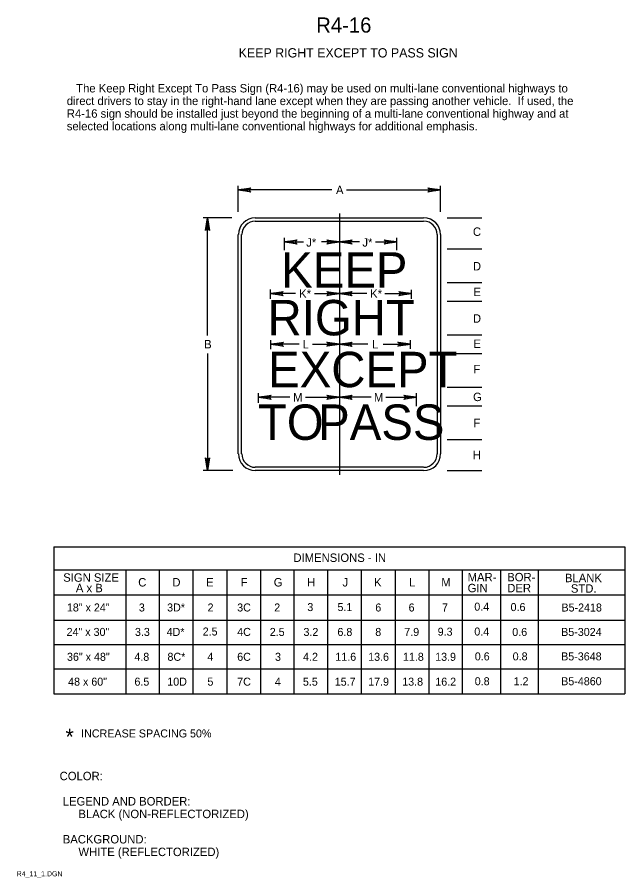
# Model space of a CAD drawing. Extents: x 0.013 to 0.193, y 0.004 to 0.259.
import ezdxf

# ---------------------------------------------------------------- set-up
doc = ezdxf.new("R2010")
doc.units = 0
for name, color, linetype in [('1', 7, 'Continuous'), ('11', 7, 'Continuous'), ('12', 7, 'Continuous'), ('2', 7, 'Continuous'), ('3', 7, 'Continuous')]:
    doc.layers.add(name, color=color, linetype=linetype)

# ---------------------------------------------------------------- blocks, each defined once
blk = doc.blocks.new('RARROW')
at = {"layer": '3'}
for p, q in [((-2.156, 0.285), (-2.2665, 0.384625)), ((-2.2665, 0.384625), (0, 0)), ((0, 0), (-2.2665, -0.379125)), ((-2.156, 0.285), (-2.075625, 0.12075)), ((0, 0), (-2.156, 0.285)), ((-2.14975, -0.2705), (0, 0)), ((-2.075625, 0.12075), (0, 0)), ((0, 0), (-2.074, -0.108)), ((-2.2665, -0.379125), (-2.14975, -0.2705)), ((-2.074, -0.108), (-2.14975, -0.2705))]:
    blk.add_line(p, q, dxfattribs=at)

msp = doc.modelspace()

# ---------------------------------------------------------------- linework, layer by layer
at = {"layer": '11'}
for p, q in [((0.08313, 0.19971), (0.13312, 0.19971)), ((0.07812, 0.12971), (0.07812, 0.19471)), ((0.13812, 0.19471), (0.13812, 0.12971)), ((0.13312, 0.12471), (0.08313, 0.12471))]:
    msp.add_line(p, q, dxfattribs=at)
for centre, start, end in [((0.08317, 0.1947), 90, 180), ((0.13317, 0.1947), 0, 90), ((0.08317, 0.1297), 180, 270), ((0.13317, 0.1297), 270, 0)]:
    msp.add_arc(centre, 0.005, start, end, dxfattribs=at)
at = {"layer": '3'}
for p, q in [((0.07812, 0.20147), (0.07812, 0.20921)), ((0.10587, 0.20796), (0.07812, 0.20796)), ((0.11025, 0.20796), (0.13812, 0.20796)), ((0.13812, 0.20147), (0.13812, 0.20921)), ((0.07625, 0.19971), (0.06775, 0.19971)), ((0.069, 0.16483), (0.069, 0.19971)), ((0.10812, 0.20096), (0.10812, 0.12346)), ((0.14012, 0.19971), (0.15038, 0.19971)), ((0.08313, 0.19871), (0.13312, 0.19871)), ((0.07913, 0.12971), (0.07913, 0.19471)), ((0.13712, 0.19471), (0.13712, 0.12971)), ((0.0918, 0.19005), (0.0918, 0.19377)), ((0.09186, 0.19252), (0.09753, 0.19252)), ((0.10877, 0.19252), (0.10285, 0.19252)), ((0.10812, 0.1939), (0.10812, 0.19127)), ((0.10812, 0.19252), (0.11188, 0.19314)), ((0.11168, 0.19296), (0.10812, 0.19252)), ((0.10812, 0.19252), (0.11156, 0.1927)), ((0.11313, 0.19252), (0.10812, 0.19252)), ((0.11156, 0.19232), (0.10812, 0.19252)), ((0.10812, 0.19252), (0.11169, 0.19206)), ((0.11188, 0.19189), (0.10812, 0.19252)), ((0.11413, 0.19252), (0.10812, 0.19252)), ((0.11156, 0.1927), (0.11168, 0.19296)), ((0.11169, 0.19206), (0.11156, 0.19232)), ((0.11188, 0.19314), (0.11168, 0.19296)), ((0.11169, 0.19206), (0.11188, 0.19189)), ((0.11887, 0.19252), (0.12514, 0.19252)), ((0.12157, 0.19299), (0.12139, 0.19315)), ((0.12139, 0.19315), (0.12514, 0.19252)), ((0.12514, 0.19252), (0.12139, 0.1919)), ((0.12139, 0.1919), (0.12158, 0.19208)), ((0.12157, 0.19299), (0.1217, 0.19272)), ((0.12514, 0.19252), (0.12157, 0.19299)), ((0.12158, 0.19208), (0.12514, 0.19252)), ((0.12171, 0.19234), (0.12158, 0.19208)), ((0.1217, 0.19272), (0.12514, 0.19252)), ((0.12514, 0.19252), (0.12171, 0.19234)), ((0.12514, 0.19005), (0.12514, 0.19377)), ((0.14012, 0.19046), (0.15038, 0.19046)), ((0.10812, 0.17921), (0.10812, 0.17596)), ((0.14012, 0.18046), (0.15038, 0.18046)), ((0.08773, 0.17571), (0.08773, 0.17846)), ((0.09508, 0.17721), (0.08816, 0.17721)), ((0.10072, 0.17721), (0.10812, 0.17721)), ((0.11623, 0.17721), (0.10867, 0.17721)), ((0.12165, 0.17721), (0.12903, 0.17721)), ((0.12948, 0.17569), (0.12948, 0.17831)), ((0.14012, 0.17496), (0.15038, 0.17496)), ((0.08775, 0.1607), (0.08775, 0.16345)), ((0.10812, 0.16358), (0.10812, 0.16096)), ((0.12926, 0.16082), (0.12926, 0.16345)), ((0.14012, 0.16496), (0.15038, 0.16496)), ((0.0962, 0.1622), (0.08818, 0.1622)), ((0.10012, 0.1622), (0.10812, 0.1622)), ((0.11658, 0.1622), (0.10812, 0.1622)), ((0.1211, 0.1622), (0.12926, 0.1622)), ((0.069, 0.15946), (0.069, 0.12471)), ((0.14012, 0.15946), (0.15038, 0.15946)), ((0.10812, 0.14846), (0.10812, 0.14521)), ((0.14012, 0.14946), (0.15038, 0.14946)), ((0.08415, 0.14483), (0.08415, 0.14771)), ((0.09346, 0.14646), (0.08415, 0.14646)), ((0.09804, 0.14646), (0.10812, 0.14646)), ((0.11757, 0.14646), (0.10812, 0.14646)), ((0.12188, 0.14646), (0.13104, 0.14646)), ((0.13104, 0.14383), (0.13104, 0.14771)), ((0.14012, 0.14396), (0.15038, 0.14396)), ((0.14012, 0.13396), (0.15038, 0.13396)), ((0.13312, 0.12571), (0.08313, 0.12571)), ((0.0765, 0.12471), (0.06775, 0.12471)), ((0.14012, 0.12471), (0.15038, 0.12471)), ((0.02344, 0.10213), (0.02344, 0.0585)), ((0.02344, 0.10212), (0.19281, 0.10212)), ((0.19281, 0.10212), (0.19281, 0.0585)), ((0.02344, 0.09525), (0.14459, 0.09525)), ((0.04474, 0.09525), (0.04474, 0.0585)), ((0.05469, 0.09525), (0.05469, 0.0585)), ((0.06469, 0.09525), (0.06469, 0.0585)), ((0.07469, 0.09525), (0.07469, 0.0585)), ((0.08469, 0.09525), (0.08469, 0.0585)), ((0.09465, 0.09525), (0.09465, 0.0585)), ((0.10459, 0.09525), (0.10459, 0.0585)), ((0.11459, 0.09525), (0.11459, 0.0585)), ((0.12464, 0.09525), (0.12464, 0.0585)), ((0.13464, 0.09525), (0.13464, 0.0585)), ((0.14459, 0.09525), (0.19281, 0.09525)), ((0.14459, 0.09525), (0.14459, 0.0585)), ((0.15597, 0.09525), (0.15597, 0.0585)), ((0.1671, 0.09525), (0.1671, 0.0585)), ((0.18005, 0.09525), (0.19281, 0.09525)), ((0.02344, 0.08787), (0.14459, 0.08787)), ((0.14459, 0.08787), (0.19281, 0.08787)), ((0.18005, 0.08788), (0.19281, 0.08788)), ((0.02344, 0.08037), (0.14459, 0.08037)), ((0.14459, 0.08037), (0.19281, 0.08037)), ((0.18005, 0.08038), (0.19281, 0.08038)), ((0.02344, 0.07312), (0.14459, 0.07312)), ((0.14459, 0.07312), (0.19281, 0.07312)), ((0.18005, 0.07313), (0.19281, 0.07313)), ((0.02344, 0.06587), (0.14459, 0.06587)), ((0.14459, 0.06587), (0.19281, 0.06587)), ((0.18005, 0.06588), (0.19281, 0.06588)), ((0.02344, 0.0585), (0.14459, 0.0585)), ((0.14459, 0.0585), (0.19281, 0.0585)), ((0.18005, 0.0585), (0.19281, 0.0585))]:
    msp.add_line(p, q, dxfattribs=at)
for centre, start, end in [((0.08317, 0.1947), 90, 180), ((0.13317, 0.1947), 0, 90), ((0.08317, 0.1297), 180, 270), ((0.13317, 0.1297), 270, 0)]:
    msp.add_arc(centre, 0.004, start, end, dxfattribs=at)

# ---------------------------------------------------------------- block references
at = {"layer": '3', "xscale": 0.0016545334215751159, "yscale": 0.0016366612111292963}
for p, rotation in [((0.07812, 0.20796), 180), ((0.069, 0.19971), 90), ((0.0918, 0.19252), 180), ((0.08773, 0.17721), 180), ((0.10812, 0.17721), 180), ((0.08775, 0.1622), 180), ((0.10812, 0.1622), 180), ((0.08415, 0.14646), 180), ((0.10812, 0.14646), 180), ((0.069, 0.12471), -90)]:
    msp.add_blockref('RARROW', p, dxfattribs=dict(at, rotation=rotation))
for p in [(0.13812, 0.20796), (0.10812, 0.19252), (0.10812, 0.17721), (0.12949, 0.17721), (0.10812, 0.1622), (0.12926, 0.1622), (0.10812, 0.14646), (0.13104, 0.14646)]:
    msp.add_blockref('RARROW', p, dxfattribs=at)

# ---------------------------------------------------------------- texts
at = {"layer": '1'}
for s, height, p in [('R4-16', 0.0045, (0.10124, 0.25462)), ('KEEP RIGHT EXCEPT TO PASS SIGN', 0.0027503, (0.07825, 0.24725)), ('COLOR:', 0.0025, (0.02513, 0.03288)), (' LEGEND AND BORDER:', 0.0024998, (0.02513, 0.02538)), ('      BLACK (NON-REFLECTORIZED)', 0.0024998, (0.02513, 0.02163)), (' BACKGROUND:', 0.0024998, (0.02513, 0.01413)), ('      WHITE (REFLECTORIZED)', 0.0024998, (0.02513, 0.01038)), ('R4_11_1.DGN', 0.0015, (0.01238, 0.00438))]:
    msp.add_text(s, height=height, dxfattribs=at).set_placement(p)
at = {"layer": '12'}
for s, p in [('KEEP', (0.09086, 0.17896)), ('RIGHT', (0.08682, 0.16483)), ('EXCEPT', (0.08699, 0.14946)), ('TO', (0.08396, 0.13383)), ('PASS', (0.10184, 0.13383))]:
    msp.add_text(s, height=0.0105, dxfattribs=at).set_placement(p)
at = {"layer": '2'}
for s, height, p in [('   The Keep Right Except To Pass Sign (R4-16) may be used on multi-lane conventional highways to ', 0.0024998, (0.02725, 0.23688)), ('direct drivers to stay in the right-hand lane except when they are passing another vehicle.  If used, the ', 0.00249975, (0.02725, 0.23313)), ('R4-16 sign should be installed just beyond the beginning of a multi-lane conventional highway and at ', 0.00249975, (0.02725, 0.22938)), ('selected locations along multi-lane conventional highways for additional emphasis.', 0.0024998, (0.02725, 0.22563))]:
    msp.add_text(s, height=height, dxfattribs=at).set_placement(p)
at = {"layer": '3'}
for s, height, p in [('A', 0.0025, (0.10712, 0.20671)), ('C', 0.0025, (0.14775, 0.19433)), ('J*', 0.0025, (0.09829, 0.19115)), ('J*', 0.0025, (0.11495, 0.19115)), ('D', 0.0025, (0.14775, 0.18408)), ('E', 0.0025, (0.14788, 0.17646)), ('K*', 0.0025, (0.0962, 0.17596)), ('K*', 0.0025, (0.11726, 0.17596)), ('D', 0.0025, (0.14775, 0.16858)), ('B', 0.0025, (0.068, 0.16096)), ('L', 0.0025, (0.09721, 0.16095)), ('L', 0.0025, (0.11786, 0.16095)), ('E', 0.0025, (0.14788, 0.16109)), ('F', 0.0025, (0.14792, 0.15358)), ('M', 0.0025, (0.09441, 0.14521)), ('M', 0.0025, (0.11838, 0.14521)), ('G', 0.0025, (0.14779, 0.14533)), ('F', 0.0025, (0.14792, 0.13759)), ('H', 0.0025, (0.14769, 0.12808)), ('DIMENSIONS - IN', 0.0024998, (0.09449, 0.09763)), ('SIGN SIZE', 0.0025, (0.02619, 0.09175)), ('C', 0.0025, (0.04844, 0.09034)), ('D', 0.0025, (0.05857, 0.09034)), ('E', 0.0025, (0.06857, 0.09034)), ('F', 0.0025, (0.07882, 0.09034)), ('G', 0.0025, (0.08866, 0.09034)), ('H', 0.0025, (0.09855, 0.09034)), ('J', 0.0025, (0.10904, 0.09034)), ('K', 0.0025, (0.11842, 0.09034)), ('L', 0.0025, (0.12878, 0.09034)), ('M', 0.0025, (0.13836, 0.09034)), ('MAR-', 0.0025, (0.14618, 0.09187)), ('BOR-', 0.0025, (0.15793, 0.09187)), ('BLANK', 0.0025, (0.17506, 0.09162)), ('A x B', 0.0025, (0.02994, 0.08863)), ('GIN', 0.0025, (0.14618, 0.08862)), ('DER', 0.0025, (0.15793, 0.08862)), ('STD.', 0.0025, (0.17681, 0.0885)), ('18" x 24"', 0.002375, (0.02728, 0.08293)), ('3', 0.00238, (0.04863, 0.08293)), ('3D*', 0.002375, (0.05701, 0.08293)), ('2', 0.00238, (0.06902, 0.08293)), ('3C', 0.002375, (0.07781, 0.08293)), ('2', 0.00238, (0.0888, 0.08293)), ('3', 0.00238, (0.09861, 0.08305)), ('5.1', 0.002375, (0.10756, 0.08305)), ('6', 0.00238, (0.11878, 0.08292)), ('6', 0.00238, (0.12866, 0.08292)), ('7', 0.00238, (0.13857, 0.08292)), ('0.4', 0.002375, (0.14816, 0.08317)), ('0.6', 0.002375, (0.15892, 0.08305)), ('B5-2418', 0.002375, (0.17401, 0.08292)), ('24" x 30"', 0.002375, (0.02719, 0.07568)), ('3.3', 0.002375, (0.04747, 0.07568)), ('4D*', 0.002375, (0.05688, 0.07568)), ('2.5', 0.002375, (0.06757, 0.0758)), ('4C', 0.002375, (0.07781, 0.07568)), ('2.5', 0.002375, (0.08747, 0.07568)), ('3.2', 0.002375, (0.09747, 0.07567)), ('6.8', 0.002375, (0.10755, 0.07567)), ('8', 0.00238, (0.11877, 0.07567)), ('7.9', 0.002375, (0.12738, 0.07567)), ('9.3', 0.002375, (0.13729, 0.07574)), ('0.4', 0.002375, (0.14816, 0.0758)), ('0.6', 0.002375, (0.15942, 0.07567)), ('B5-3024', 0.002375, (0.17392, 0.07567)), ('36" x 48"', 0.002375, (0.02731, 0.0683)), ('4.8', 0.002375, (0.0473, 0.0683)), ('8C*', 0.002375, (0.05712, 0.0683)), ('4', 0.00238, (0.06895, 0.0683)), ('6C', 0.002375, (0.07781, 0.0683)), ('3', 0.00238, (0.08903, 0.0683)), ('4.2', 0.002375, (0.09735, 0.0683)), ('11.6', 0.002375, (0.10693, 0.0683)), ('13.6', 0.002375, (0.11666, 0.0683)), ('11.8', 0.002375, (0.12699, 0.0683)), ('13.9', 0.002375, (0.13654, 0.0683)), ('0.6', 0.002375, (0.1483, 0.06842)), ('0.8', 0.002375, (0.15954, 0.06842)), ('B5-3648', 0.002375, (0.17392, 0.06842)), ('48 x 60"', 0.002375, (0.02764, 0.06093)), ('6.5', 0.002375, (0.04732, 0.06093)), ('10D', 0.002375, (0.05707, 0.06093)), ('5', 0.00238, (0.06897, 0.06093)), ('7C', 0.002375, (0.07781, 0.06093)), ('4', 0.00238, (0.08899, 0.06093)), ('5.5', 0.002375, (0.0973, 0.06092)), ('15.7', 0.002375, (0.10675, 0.06092)), ('17.9', 0.002375, (0.11666, 0.06092)), ('13.8', 0.002375, (0.12677, 0.06092)), ('16.2', 0.002375, (0.13658, 0.06092)), ('0.8', 0.002375, (0.14829, 0.06105)), ('1.2', 0.002375, (0.15982, 0.06105)), ('B5-4860', 0.002375, (0.17393, 0.06105)), ('*', 0.00475, (0.02687, 0.04339)), ('INCREASE SPACING 50%', 0.0023752, (0.03151, 0.04557))]:
    msp.add_text(s, height=height, dxfattribs=at).set_placement(p)

doc.saveas('drawing.dxf')
